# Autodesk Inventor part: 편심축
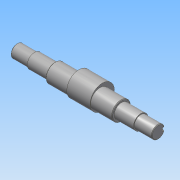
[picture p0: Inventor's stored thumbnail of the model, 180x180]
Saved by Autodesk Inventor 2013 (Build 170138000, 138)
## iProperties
Created: 2015-10
Part Number: 편심축
Document SubType Name: Modeling
Designer: mdu
Density: 7.86 g/cm^3
Material: 강철, 연강
Mass: 1327.93 g
Surface Area: 248.525 cm^2
Volume: 168.947 cm^3
Author: mdu
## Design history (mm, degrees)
sketch "스케치1"
  geometry: L1 (-20.5, -41.331)-(-20.5, 32.669) reference; L2 (7.5, -30.031)-(7.5, 21.369) reference; L3 (135.5, -30.331)-(135.5, 21.669) reference; L4 (121.5, 21.369)-(121.5, -30.031) reference; L5 (184.5, -4.331)-(-57.5, -4.331); L6 (184.5, -4.331)-(184.5, 6.669); L7 (154.5, 8.169)-(121.5, 8.169); L8 (121.5, 8.169)-(121.5, 11.669); L9 (121.5, 11.669)-(7.5, 11.669); L10 (7.5, 11.669)-(7.5, 8.169); L11 (7.5, 8.169)-(-27.5, 8.169); L12 (-27.5, 8.169)-(-27.5, 6.669); L13 (-27.5, 6.669)-(-57.5, 6.669); L14 (-57.5, 6.669)-(-57.5, -4.331); L15 (154.5, 8.169)-(154.5, 6.669); L16 (154.5, 6.669)-(184.5, 6.669); C1 r 32.5 at (64.5, -4.331) reference; 1 further point
  constraints: 24 end point, 8 perpendicular, 5 point on line, 3 parallel, 2 collinear
  dimensions: "d1" = 25 diameter of L11 L5; "d2" = 32 diameter of L9 L5; "d3" = 22 diameter of L13 L5; "d4" = 35 distance of L10.end L11.end; "d5" = 30 distance of L12.end L13.end; "d15" = 33 distance of L7.start L7.end; "d26" = 30 distance of L15.end L6.end
revolve "회전1" sketch "스케치1" stored, may be unused: angle "d6" = 90 deg
node "작업 평면1"
sketch "스케치2"
  geometry: C1 r 16 at (0, 0) reference; C2 r 16 at (0, 0) reference; C3 r 20.75 at (0, 4); C4 r 16 at (0, 0) reference; 1 further point
  constraints: 1 centre point, 1 vertical alignment
  dimensions: "d8" = 41.5 diameter of C3; "d25" = 4 distance of C3.centre C1.centre
extrude "돌출1" join sketch "스케치2" stored distance "d9" = 40; taper "d10" = 0 deg
chamfer "모따기1" distance "d11" = 1; stored, may be unused: second distance "d12" = 2, angle "d13" = 45 deg
node "작업 평면2"
sketch "스케치3"
  geometry: L1 (-15, -10)-(-15, 10) reference; L2 (-15, 3)-(0, 3); L3 (0, -3)-(-15, -3); A1 r 3 centre (0, 0) between (0, -3) and (0, 3); 2 further points
  constraints: 4 end point, 2 perpendicular, 2 point on circle, 2 point on line, 2 tangent, 1 centre point, 1 horizontal alignment, 1 midpoint
  dimensions: "d16" = 18 dimension on A1 L1; "d17" = 6 distance between parallel lines of L3 L2
extrude "돌출2" cut sketch "스케치3" distance "d18" = 3.5; taper "d19" = 0 deg
node "작업 평면3"
node "솔리드1"
mirror "대칭1"
node "참조1"
node "참조2"
node "참조3"
node "참조4"
node "참조5"
node "투영된 루프1"
